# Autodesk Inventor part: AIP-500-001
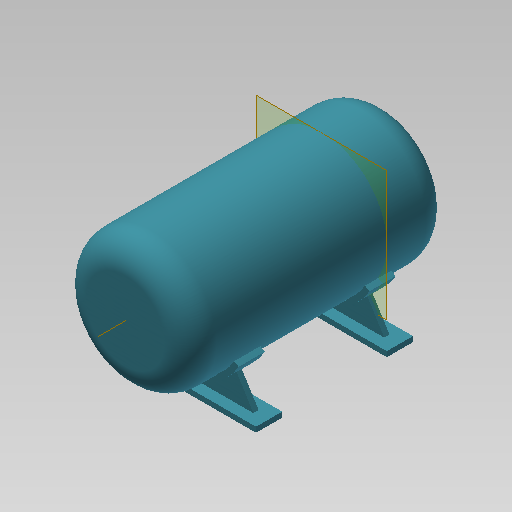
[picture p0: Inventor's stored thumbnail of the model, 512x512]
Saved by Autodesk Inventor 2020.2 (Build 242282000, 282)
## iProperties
Created: 2014-06
Part Number: AIP-500-001
Material: Ogólny
Document SubType Name: Modeling
Designer: F.Stasiak
Density: 1 g/cm^3
Appearance: Niebieska z odcieniem szarości
Catalog Web Link: www.expertbooks.pl
Manager: www.cadconsulting.pl
Company: Fabian Stasiak CAD Consulting
Author: F.Stasiak
Subject: Zbiór ćwiczeń. Autodesk Inventor 2020. Kurs Professional
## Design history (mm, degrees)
sketch "Szkic1"
  geometry: C1 r 250 at (0, 0); 1 further point
  constraints: 1 centre point, 1 coincident
  dimensions: "d0" = 500 diameter of C1
extrude "Wyciągnięcie proste1" new body sketch "Szkic1" stored distance "d1" = 1000; taper "d2" = 0 deg
fillet "Zaokrąglenie1" dims "d3" = 100
node "Płaszczyzna konstrukcyjna1"
sketch "Szkic2"
  geometry: L1 (-175, -178.536)-(-250, -300); L2 (-250, -300)-(250, -300); L3 (250, -300)-(175, -178.536); L4 (-175, -178.536)-(175, -178.536); A1 r 250 centre (0, 0) between (-175, -178.536) and (175, -178.536) reference; 2 further points
  constraints: 8 end point, 2 point on circle, 1 horizontal, 1 midpoint, 1 parallel, 1 vertical alignment
  dimensions: "d6" = 300 distance from line of point (0, 0) L2; "d7" = 500 distance of L1.end L2.end; "d8" = 350 distance of L1.start L3.end
extrude "Wyciągnięcie proste2" join sketch "Szkic2" stored distance "d9" = 20; taper "d10" = 0 deg
sketch "Szkic3"
  geometry: L1 (-250, -300)-(250, -300) reference; L2 (-300, -300)-(300, -300); L3 (300, -300)-(300, -320); L4 (300, -320)-(-300, -320); L5 (-300, -320)-(-300, -300); 2 further points
  constraints: 8 end point, 2 midpoint, 2 parallel, 1 horizontal, 1 perpendicular
  dimensions: "d11" = 600 distance of L3.end L4.end; "d12" = 20 distance of L2.end L3.end
extrude "Wyciągnięcie proste3" join sketch "Szkic3" stored distance "d13" = 100; taper "d14" = 0 deg
node "Oś konstrukcyjna1"
sketch "Szkic4"
  geometry: L1 (-250, -400)-(-250, 400) reference; L2 (-250, -300)-(-270, -300); L3 (-270, -300)-(-270, -200); L4 (-270, -200)-(-250, -200); L5 (-250, -200)-(-250, -300); L6 (-300, -200)-(-300, -300) reference; L7 (0, -700)-(0, 700) reference; 3 further points
  constraints: 8 end point, 2 midpoint, 2 parallel, 1 collinear, 1 horizontal, 1 horizontal alignment, 1 perpendicular
  dimensions: "d15" = 20 distance of L3.end L4.end; "d16" = 100 distance of L2.end L3.end
revolve "Obrót1" sketch "Szkic4" stored, may be unused: angle "d17" = 120 deg
mirror "Odbicie lustrzane1"
sketch "Szkic5"
  geometry: C1 r 150 at (0, 0) reference; C2 r 20 at (0, -150)
  constraints: 1 centre point
  dimensions: "d18" = 40 diameter of C2; "d19" = 150 distance of C1.centre C2.centre
extrude "Wyciągnięcie proste4" join sketch "Szkic5" distance "d20" = 50; taper "d21" = 0 deg
sketch "Szkic6"
  geometry: C1 r 20 at (0, 0) reference; 1 further point
hole "Otwór1" sketch "Szkic6" at (0, 0) diameter "d22" = 21.971; stored, may be unused: countersink angle "d26" = 90 deg, drill point angle "d28" = 118 deg; dims "d23" = 13, "d24" = 4, "d25" = 2, "d27" = 12
node "Bryła1"
